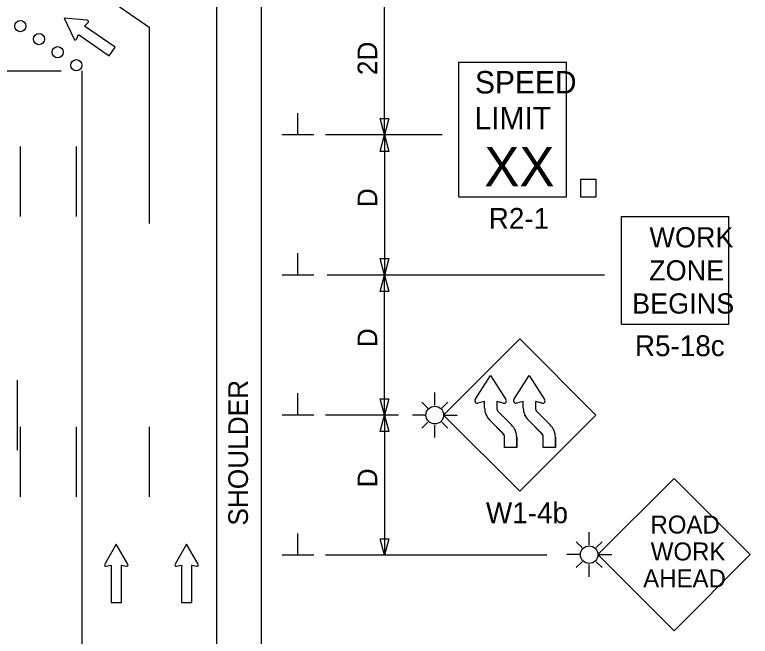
# Model space of a CAD drawing. Extents: x 16765 to 18475, y 6981 to 8262.
# Drawn here: x 17041.1 to 17303.7, y 7413.7 to 7635.5 of the extents above; entities that cross this region are included whole.
import ezdxf

# ---------------------------------------------------------------- set-up
doc = ezdxf.new("R2010")
doc.units = 0
for name, color, linetype in [('ALI_LEGAL_EX', 7, 'Continuous'), ('MT_SCRATCH_LEVEL_E', 7, 'Continuous'), ('PAVT_EDGE_EX', 7, 'Continuous'), ('TRAFFIC_SIGNS_PR', 7, 'Continuous'), ('TYPICAL_TEXT_DIMEN_PR', 7, 'Continuous')]:
    doc.layers.add(name, color=color, linetype=linetype)

msp = doc.modelspace()

# ---------------------------------------------------------------- linework, layer by layer
at = {"layer": 'ALI_LEGAL_EX'}
for points in [[(17043.08, 7588.47), (17043.08, 7563.47)], [(17063.08, 7588.47), (17063.08, 7563.47)], [(17089.08, 7588.47), (17089.08, 7563.47)], [(17043.08, 7488.47), (17043.08, 7463.47)], [(17063.08, 7488.47), (17063.08, 7463.47)], [(17089.08, 7488.47), (17089.08, 7463.47)]]:
    msp.add_lwpolyline(points, dxfattribs=at)
at = {"layer": 'MT_SCRATCH_LEVEL_E'}
for p, q in [((17058.7, 7634.3), (17062.28, 7626.78)), ((17067.01, 7633.55), (17058.7, 7634.3)), ((17058.7, 7634.3), (17062.28, 7626.78)), ((17067.01, 7633.55), (17058.7, 7634.3)), ((17066.02, 7631.49), (17067.3, 7632.77)), ((17066.02, 7631.49), (17067.3, 7632.77)), ((17076.89, 7623.9), (17066.02, 7631.49)), ((17076.89, 7623.9), (17066.02, 7631.49)), ((17063.12, 7626.78), (17063.88, 7628.42)), ((17063.12, 7626.78), (17063.88, 7628.42)), ((17063.88, 7628.42), (17074.75, 7620.83)), ((17063.88, 7628.42), (17074.75, 7620.83)), ((17074.75, 7620.83), (17076.89, 7623.9)), ((17074.75, 7620.83), (17076.89, 7623.9)), ((17077.36, 7446.6), (17073.25, 7439.36)), ((17077.36, 7446.6), (17073.25, 7439.36)), ((17081.51, 7439.36), (17077.36, 7446.6)), ((17081.51, 7439.36), (17077.36, 7446.6)), ((17102.45, 7446.6), (17098.34, 7439.36)), ((17102.45, 7446.6), (17098.34, 7439.36)), ((17106.6, 7439.36), (17102.45, 7446.6)), ((17106.6, 7439.36), (17102.45, 7446.6)), ((17073.73, 7438.67), (17075.51, 7438.99)), ((17073.73, 7438.67), (17075.51, 7438.99)), ((17075.51, 7438.99), (17075.51, 7425.73)), ((17075.51, 7438.99), (17075.51, 7425.73)), ((17079.25, 7425.73), (17079.25, 7438.99)), ((17079.25, 7438.99), (17081.03, 7438.67)), ((17079.25, 7425.73), (17079.25, 7438.99)), ((17079.25, 7438.99), (17081.03, 7438.67)), ((17098.82, 7438.67), (17100.6, 7438.99)), ((17098.82, 7438.67), (17100.6, 7438.99)), ((17100.6, 7438.99), (17100.6, 7425.73)), ((17100.6, 7438.99), (17100.6, 7425.73)), ((17104.34, 7425.73), (17104.34, 7438.99)), ((17104.34, 7438.99), (17106.12, 7438.67)), ((17104.34, 7425.73), (17104.34, 7438.99)), ((17104.34, 7438.99), (17106.12, 7438.67)), ((17075.51, 7425.73), (17079.25, 7425.73)), ((17075.51, 7425.73), (17079.25, 7425.73)), ((17100.6, 7425.73), (17104.34, 7425.73)), ((17100.6, 7425.73), (17104.34, 7425.73))]:
    msp.add_line(p, q, dxfattribs=at)
for centre, start, end in [((17066.96, 7633.09), 315.105, 84.8419), ((17066.96, 7633.09), 315.105, 84.8419), ((17062.7, 7626.99), 205.4936, 335.0326), ((17062.7, 7626.99), 205.4936, 335.0326), ((17073.66, 7439.13), 150.4248, 279.9638), ((17073.66, 7439.13), 150.4248, 279.9638), ((17081.1, 7439.13), 260.0362, 29.7731), ((17081.1, 7439.13), 260.0362, 29.7731), ((17098.75, 7439.13), 150.4248, 279.9638), ((17098.75, 7439.13), 150.4248, 279.9638), ((17106.19, 7439.13), 260.0362, 29.7731), ((17106.19, 7439.13), 260.0362, 29.7731)]:
    msp.add_arc(centre, 0.463, start, end, dxfattribs=at)
at = {"layer": 'PAVT_EDGE_EX'}
for p, q in [((17113.08, 8196.54), (17113.08, 7351.89)), ((17129.08, 8196.54), (17129.08, 7351.89)), ((17065.08, 7647.81), (17089.08, 7631.05)), ((17089.08, 7631.05), (17089.08, 7561)), ((17065.08, 7615.49), (17065.08, 7351.89))]:
    msp.add_line(p, q, dxfattribs=at)
msp.add_lwpolyline([(17042.08, 7480.11), (17042.08, 7505.11)], dxfattribs=at)
at = {"layer": 'TRAFFIC_SIGNS_PR'}
for p, q in [((17199.65, 7618.55), (17238.05, 7618.55)), ((17199.65, 7570.55), (17199.65, 7618.55)), ((17238.05, 7570.55), (17238.05, 7618.55)), ((17199.65, 7570.55), (17238.05, 7570.55)), ((17257.71, 7525.1), (17257.71, 7563.5)), ((17257.71, 7563.5), (17296.11, 7563.5)), ((17296.11, 7525.1), (17296.11, 7563.5)), ((17257.71, 7525.1), (17296.11, 7525.1)), ((17194.23, 7492.62), (17221.38, 7519.78)), ((17221.38, 7519.78), (17248.53, 7492.62)), ((17191.07, 7496.18), (17191.07, 7500.68)), ((17188.56, 7495.14), (17186.45, 7497.24)), ((17193.59, 7495.14), (17195.69, 7497.24)), ((17218.45, 7489.16), (17213.74, 7493.87)), ((17213.74, 7493.87), (17218.45, 7489.16)), ((17232.25, 7489.16), (17227.53, 7493.87)), ((17227.53, 7493.87), (17232.25, 7489.16)), ((17187.92, 7492.62), (17183.08, 7492.62)), ((17194.23, 7492.62), (17199.11, 7492.62)), ((17221.38, 7465.47), (17194.23, 7492.62)), ((17215.4, 7486.11), (17210.68, 7490.82)), ((17215.4, 7486.1), (17210.68, 7490.82)), ((17248.53, 7492.62), (17221.38, 7465.47)), ((17229.19, 7486.11), (17224.48, 7490.82)), ((17229.19, 7486.1), (17224.48, 7490.82)), ((17188.56, 7490.11), (17186.45, 7488)), ((17191.07, 7484.66), (17191.07, 7489.07)), ((17193.59, 7490.11), (17195.69, 7488)), ((17216, 7481.04), (17216, 7484.74)), ((17220.32, 7481.04), (17220.32, 7484.74)), ((17229.8, 7481.04), (17229.8, 7484.74)), ((17234.11, 7481.04), (17234.11, 7484.74)), ((17220.32, 7481.04), (17216, 7481.04)), ((17234.11, 7481.04), (17229.8, 7481.04)), ((17276.53, 7469.98), (17249.34, 7442.8)), ((17303.72, 7442.8), (17276.53, 7469.98)), ((17246.19, 7446.35), (17246.19, 7450.85)), ((17243.68, 7445.31), (17241.57, 7447.42)), ((17248.7, 7445.31), (17250.81, 7447.42)), ((17243.04, 7442.8), (17238.2, 7442.8)), ((17249.34, 7442.8), (17276.53, 7415.61)), ((17249.34, 7442.8), (17254.23, 7442.8)), ((17276.53, 7415.61), (17303.72, 7442.8)), ((17243.68, 7440.28), (17241.57, 7438.18)), ((17246.19, 7434.83), (17246.19, 7439.24)), ((17248.7, 7440.28), (17250.81, 7438.18))]:
    msp.add_line(p, q, dxfattribs=at)
msp.add_lwpolyline([(17243.07, 7570.55), (17248.66, 7570.55), (17248.66, 7576.72), (17243.07, 7576.72)], close=True, dxfattribs=at)
for points in [[(17205.53, 7498.15), (17211.01, 7506.76), (17216.49, 7498.15)], [(17205.53, 7498.15), (17211.01, 7506.76), (17216.49, 7498.15)], [(17219.33, 7498.15), (17224.81, 7506.76), (17230.29, 7498.15)], [(17219.33, 7498.15), (17224.81, 7506.76), (17230.29, 7498.15)], [(17208.86, 7495.13), (17208.86, 7497.5), (17206.49, 7496.85)], [(17208.86, 7495.13), (17208.86, 7497.5), (17206.49, 7496.85)], [(17215.53, 7496.85), (17213.17, 7497.5), (17213.18, 7495.2)], [(17215.53, 7496.85), (17214.7, 7497.08), (17213.17, 7497.5), (17213.18, 7495.2)], [(17222.66, 7495.13), (17222.65, 7497.5), (17220.29, 7496.85)], [(17222.66, 7495.13), (17222.65, 7497.5), (17220.29, 7496.85)], [(17229.33, 7496.85), (17226.97, 7497.5), (17226.97, 7495.2)], [(17229.33, 7496.85), (17228.49, 7497.08), (17226.97, 7497.5), (17226.97, 7495.2)], [(17220.32, 7484.74), (17220.32, 7481.04), (17216, 7481.04), (17216, 7484.74)], [(17234.11, 7484.74), (17234.11, 7481.04), (17229.8, 7481.04), (17229.8, 7484.74)]]:
    msp.add_lwpolyline(points, dxfattribs=at)
for centre, radius in [((17043.08, 7631.46), 2), ((17043.08, 7631.46), 2), ((17049.75, 7626.81), 2), ((17056.41, 7622.15), 2), ((17063.08, 7617.49), 2), ((17191.07, 7492.62), 3.15), ((17246.19, 7442.8), 3.15)]:
    msp.add_circle(centre, radius, dxfattribs=at)
for centre, radius, start, end in [((17206.26, 7497.68), 0.866, 147.7292, 285.3172), ((17206.26, 7497.68), 0.866, 147.7196, 285.3201), ((17196.42, 7503.94), 10.8, 327.5335, 327.5431), ((17209.34, 7486.43), 10.8, 105.3192, 105.32), ((17215.76, 7497.68), 0.864, 254.6014, 32.4796), ((17215.76, 7497.68), 0.866, 254.6148, 32.4712), ((17220.06, 7497.68), 0.866, 147.7292, 285.3172), ((17220.06, 7497.68), 0.866, 147.7196, 285.3201), ((17210.22, 7503.94), 10.8, 327.5335, 327.5431), ((17223.14, 7486.43), 10.8, 105.3192, 105.32), ((17229.56, 7497.68), 0.864, 254.6014, 32.4796), ((17229.56, 7497.68), 0.866, 254.6148, 32.4712), ((17215.03, 7495.2), 6.17, 180.6181, 225.7875), ((17215.03, 7495.2), 6.17, 180.6245, 225.2313), ((17215.03, 7495.2), 1.85, 180, 225.7875), ((17215.03, 7495.2), 1.85, 179.8762, 225.7877), ((17228.82, 7495.2), 6.17, 180.6181, 225.7875), ((17228.82, 7495.2), 6.17, 180.6245, 225.2313), ((17228.82, 7495.2), 1.85, 180, 225.7875), ((17228.82, 7495.2), 1.85, 179.8762, 225.7877), ((17214.15, 7484.74), 6.17, 0, 45.7875), ((17214.15, 7484.74), 6.17, 0, 45.7875), ((17214.15, 7484.74), 6.17, 0, 45.7883), ((17227.95, 7484.74), 6.17, 0, 45.7875), ((17227.95, 7484.74), 6.17, 0, 45.7875), ((17227.95, 7484.74), 6.17, 0, 45.7883), ((17214.15, 7484.74), 1.85, 0, 47.628), ((17214.15, 7484.74), 1.85, 0, 45.7875), ((17227.95, 7484.74), 1.85, 0, 47.628), ((17227.95, 7484.74), 1.85, 0, 45.7875)]:
    msp.add_arc(centre, radius, start, end, dxfattribs=at)
at = {"layer": 'TYPICAL_TEXT_DIMEN_PR'}
for p, q in [((17173.08, 7592.61), (17173.08, 7642.61)), ((16927.98, 7615.49), (17057.62, 7615.49)), ((17142.21, 7592.61), (17142.21, 7600.39)), ((17173.08, 7592.61), (17171.51, 7598.47)), ((17171.51, 7598.47), (17173.08, 7598.47)), ((17173.08, 7598.47), (17174.65, 7598.47)), ((17174.65, 7598.47), (17173.08, 7592.61)), ((17147.83, 7592.61), (17136.58, 7592.61)), ((17193.71, 7592.61), (17152.08, 7592.61)), ((17171.51, 7586.74), (17173.08, 7592.61)), ((17173.08, 7592.61), (17174.65, 7586.74)), ((17173.08, 7592.61), (17173.08, 7542.61)), ((17173.08, 7586.74), (17171.51, 7586.74)), ((17174.65, 7586.74), (17173.08, 7586.74)), ((17142.21, 7542.61), (17142.21, 7550.39)), ((17173.08, 7542.61), (17171.51, 7548.47)), ((17171.51, 7548.47), (17173.08, 7548.47)), ((17173.08, 7548.47), (17174.65, 7548.47)), ((17174.65, 7548.47), (17173.08, 7542.61)), ((17147.83, 7542.61), (17136.58, 7542.61)), ((17251.69, 7542.61), (17152.63, 7542.61)), ((17171.51, 7536.74), (17173.08, 7542.61)), ((17173.08, 7542.61), (17174.65, 7536.74)), ((17173.08, 7492.61), (17173.08, 7542.61)), ((17173.08, 7536.74), (17171.51, 7536.74)), ((17174.65, 7536.74), (17173.08, 7536.74)), ((17142.21, 7492.61), (17142.21, 7500.39)), ((17173.08, 7492.61), (17171.51, 7498.47)), ((17171.51, 7498.47), (17173.08, 7498.47)), ((17173.08, 7498.47), (17174.65, 7498.47)), ((17174.65, 7498.47), (17173.08, 7492.61)), ((17147.83, 7492.61), (17136.58, 7492.61)), ((17178.08, 7492.61), (17152.08, 7492.61)), ((17171.51, 7486.74), (17173.08, 7492.61)), ((17173.08, 7492.61), (17174.65, 7486.74)), ((17173.08, 7492.61), (17173.08, 7442.61)), ((17173.08, 7486.74), (17171.51, 7486.74)), ((17174.65, 7486.74), (17173.08, 7486.74)), ((17142.21, 7442.61), (17142.21, 7450.39)), ((17173.08, 7442.61), (17171.51, 7448.47)), ((17171.51, 7448.47), (17173.08, 7448.47)), ((17173.08, 7448.47), (17174.65, 7448.47)), ((17174.65, 7448.47), (17173.08, 7442.61)), ((17147.83, 7442.61), (17136.58, 7442.61)), ((17231.06, 7442.61), (17152.08, 7442.61))]:
    msp.add_line(p, q, dxfattribs=at)

# ---------------------------------------------------------------- texts
at = {"layer": 'TRAFFIC_SIGNS_PR'}
for s, height, p in [('SPEED', 8, (17205.42, 7607.41)), ('LIMIT', 8, (17205.26, 7594.61)), ('XX', 14.031, (17208.76, 7574.31)), ('R2-1', 7.44, (17210.33, 7559.11)), ('WORK', 7.217, (17267.71, 7552.47)), ('ZONE', 7.217, (17267.59, 7540.66)), ('BEGINS', 7.217, (17261.52, 7528.85)), ('R5-18c', 7.44, (17262.52, 7513.66)), ('W1-4b', 7.44, (17209.33, 7454.03)), ('ROAD', 6.408, (17268.06, 7450.34)), ('WORK', 6.408, (17268.17, 7440.73)), ('AHEAD', 6.408, (17265.48, 7431.12))]:
    msp.add_text(s, height=height, dxfattribs=at).set_placement(p)
at = {"layer": 'TYPICAL_TEXT_DIMEN_PR'}
for s, p in [('2D', (17170.52, 7613.95)), ('D', (17170.52, 7566.82)), ('D', (17170.52, 7516.82)), ('SHOULDER', (17124.36, 7453.16)), ('D', (17170.52, 7466.82))]:
    msp.add_text(s, height=7, rotation=90, dxfattribs=at).set_placement(p)

doc.saveas('drawing.dxf')
